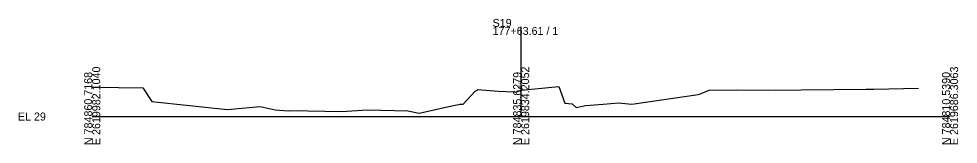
# Model space of a CAD drawing. Extents: x 1274 to 1603, y -10 to 1051.
# Drawn here: x 1274.3 to 1602.9, y -9.7 to 34.2 of the extents above; entities that cross this region are included whole.
import ezdxf

# ---------------------------------------------------------------- set-up
doc = ezdxf.new("R2010")
doc.units = 0
for name, color, linetype in [('RD_GPK_XS_Cell', 7, 'Continuous'), ('RD_XS_ExGround', 7, 'Continuous'), ('RD_XS_TX_Elev_EX', 7, 'Continuous')]:
    doc.layers.add(name, color=color, linetype=linetype)

msp = doc.modelspace()

# ---------------------------------------------------------------- linework, layer by layer
at = {"layer": 'RD_GPK_XS_Cell'}
for p, q in [((1450.01, 0), (1450.01, 31.36)), ((1300, 0), (1450.01, 0)), ((1450.01, 0), (1600.02, 0))]:
    msp.add_line(p, q, dxfattribs=at)
at = {"layer": 'RD_XS_ExGround'}
for p, q in [((1300, 10.27), (1309.13, 10.15)), ((1309.13, 10.15), (1317.66, 10.04)), ((1317.66, 10.04), (1320.8, 5.2)), ((1450.01, 9.17), (1463.14, 10.45)), ((1463.14, 10.45), (1465.26, 4.63)), ((1573.41, 9.6), (1588.96, 9.87)), ((1429.78, 4.33), (1433.92, 8.82)), ((1433.92, 8.82), (1434.64, 9.28)), ((1434.64, 9.28), (1434.85, 9.47)), ((1434.85, 9.47), (1442.02, 8.87)), ((1442.02, 8.87), (1447.51, 8.65)), ((1447.51, 8.65), (1448.01, 8.56)), ((1448.01, 8.56), (1449.62, 9.13)), ((1449.62, 9.13), (1450.01, 9.17)), ((1488.72, 4.27), (1511.94, 7.74)), ((1511.94, 7.74), (1512.42, 7.81)), ((1512.42, 7.81), (1515.72, 9.26)), ((1515.72, 9.26), (1525.35, 9.31)), ((1525.35, 9.31), (1536.68, 9.19)), ((1536.68, 9.19), (1570.55, 9.62)), ((1570.55, 9.62), (1571.54, 9.62)), ((1571.54, 9.62), (1573.41, 9.6)), ((1320.8, 5.2), (1347.17, 2.51)), ((1347.17, 2.51), (1358.67, 3.53)), ((1358.67, 3.53), (1364.02, 2.29)), ((1414.29, 1.17), (1425.72, 3.79)), ((1425.72, 3.79), (1428.05, 4.23)), ((1428.05, 4.23), (1428.55, 4.28)), ((1428.55, 4.28), (1429.78, 4.33)), ((1465.26, 4.63), (1467.83, 4.42)), ((1467.83, 4.42), (1469.29, 3.11)), ((1469.29, 3.11), (1472.65, 3.87)), ((1472.65, 3.87), (1478.69, 4.27)), ((1478.69, 4.27), (1484.04, 4.74)), ((1484.04, 4.74), (1488.72, 4.27)), ((1364.02, 2.29), (1368.56, 1.98)), ((1368.56, 1.98), (1369.57, 2.06)), ((1369.57, 2.06), (1387.23, 1.73)), ((1387.23, 1.73), (1396.24, 2.3)), ((1396.24, 2.3), (1410.43, 1.94)), ((1410.43, 1.94), (1414.29, 1.17))]:
    msp.add_line(p, q, dxfattribs=at)

# ---------------------------------------------------------------- texts
at = {"layer": 'RD_GPK_XS_Cell'}
for s, p in [('S19', (1440.01, 31.36)), ('177+63.61 / 1', (1440.01, 28.56)), ('EL 29', (1274, -1.4))]:
    msp.add_text(s, height=2.8, dxfattribs=at).set_placement(p)
for s, p in [('E 2619982.1040', (1302.8, -10)), ('E 2619834.2052', (1452.81, -10)), ('E 2619686.3063', (1602.82, -10)), ('N 784860.7168', (1300, -10)), ('N 784835.6279', (1450.01, -10)), ('N 784810.5390', (1600.02, -10))]:
    msp.add_text(s, height=2.8, rotation=90, dxfattribs=at).set_placement(p)
at = {"layer": 'RD_XS_TX_Elev_EX'}
msp.add_text('38.17', height=0.8, rotation=90, dxfattribs=at).set_placement((1449.91, 9.67))

doc.saveas('drawing.dxf')
